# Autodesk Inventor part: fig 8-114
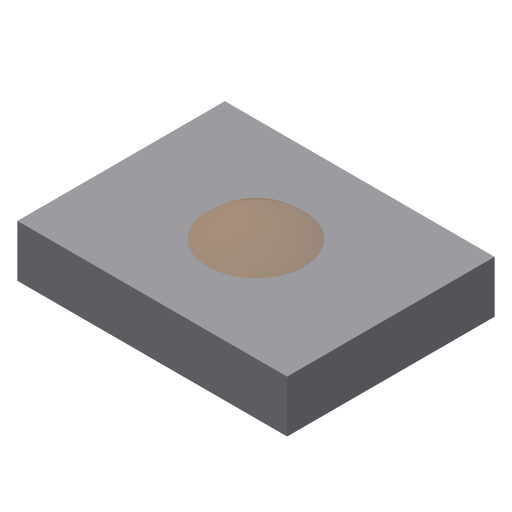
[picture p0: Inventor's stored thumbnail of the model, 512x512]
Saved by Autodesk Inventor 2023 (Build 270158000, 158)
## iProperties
Created: 2009-09
Part Number: fig 8-114
Document SubType Name: Modeling
Designer: Sham
Density: 1 g/cm^3
Material: Generic
Appearance: Default
Author: Sham
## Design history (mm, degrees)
sketch "Sketch1"
  geometry: L1 (-26, 20)-(0, 20); L2 (0, 20)-(0, 0); L3 (0, 0)-(-26, 0); L4 (-26, 0)-(-26, 20)
  constraints: 8 end point, 2 parallel, 1 horizontal, 1 perpendicular
extrude "Extrusion1" new body sketch "Sketch1" distance "d0" = 5; taper "d1" = 0 deg
workplane "Work Plane1"
sketch "Sketch2"
  geometry: L1 (13, 8)-(13, 5); A1 r 7.517 centre (12.377, -0.349) between (17.658, 5) and (13, 7.142)
  constraints: 2 end point, 2 point on circle, 1 centre point
feature "RevolutionSrf2" sketch "Sketch2" dims angle "d4" = 90 deg
body "Solid1"
body "Srf2"
